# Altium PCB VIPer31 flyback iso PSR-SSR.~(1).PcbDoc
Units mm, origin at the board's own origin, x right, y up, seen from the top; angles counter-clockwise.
Board outline 152.4 x 101.6 mm, 2 copper layers (Top Layer, Bottom Layer); 56 components, 32 nets, 138 pads, 6 vias.
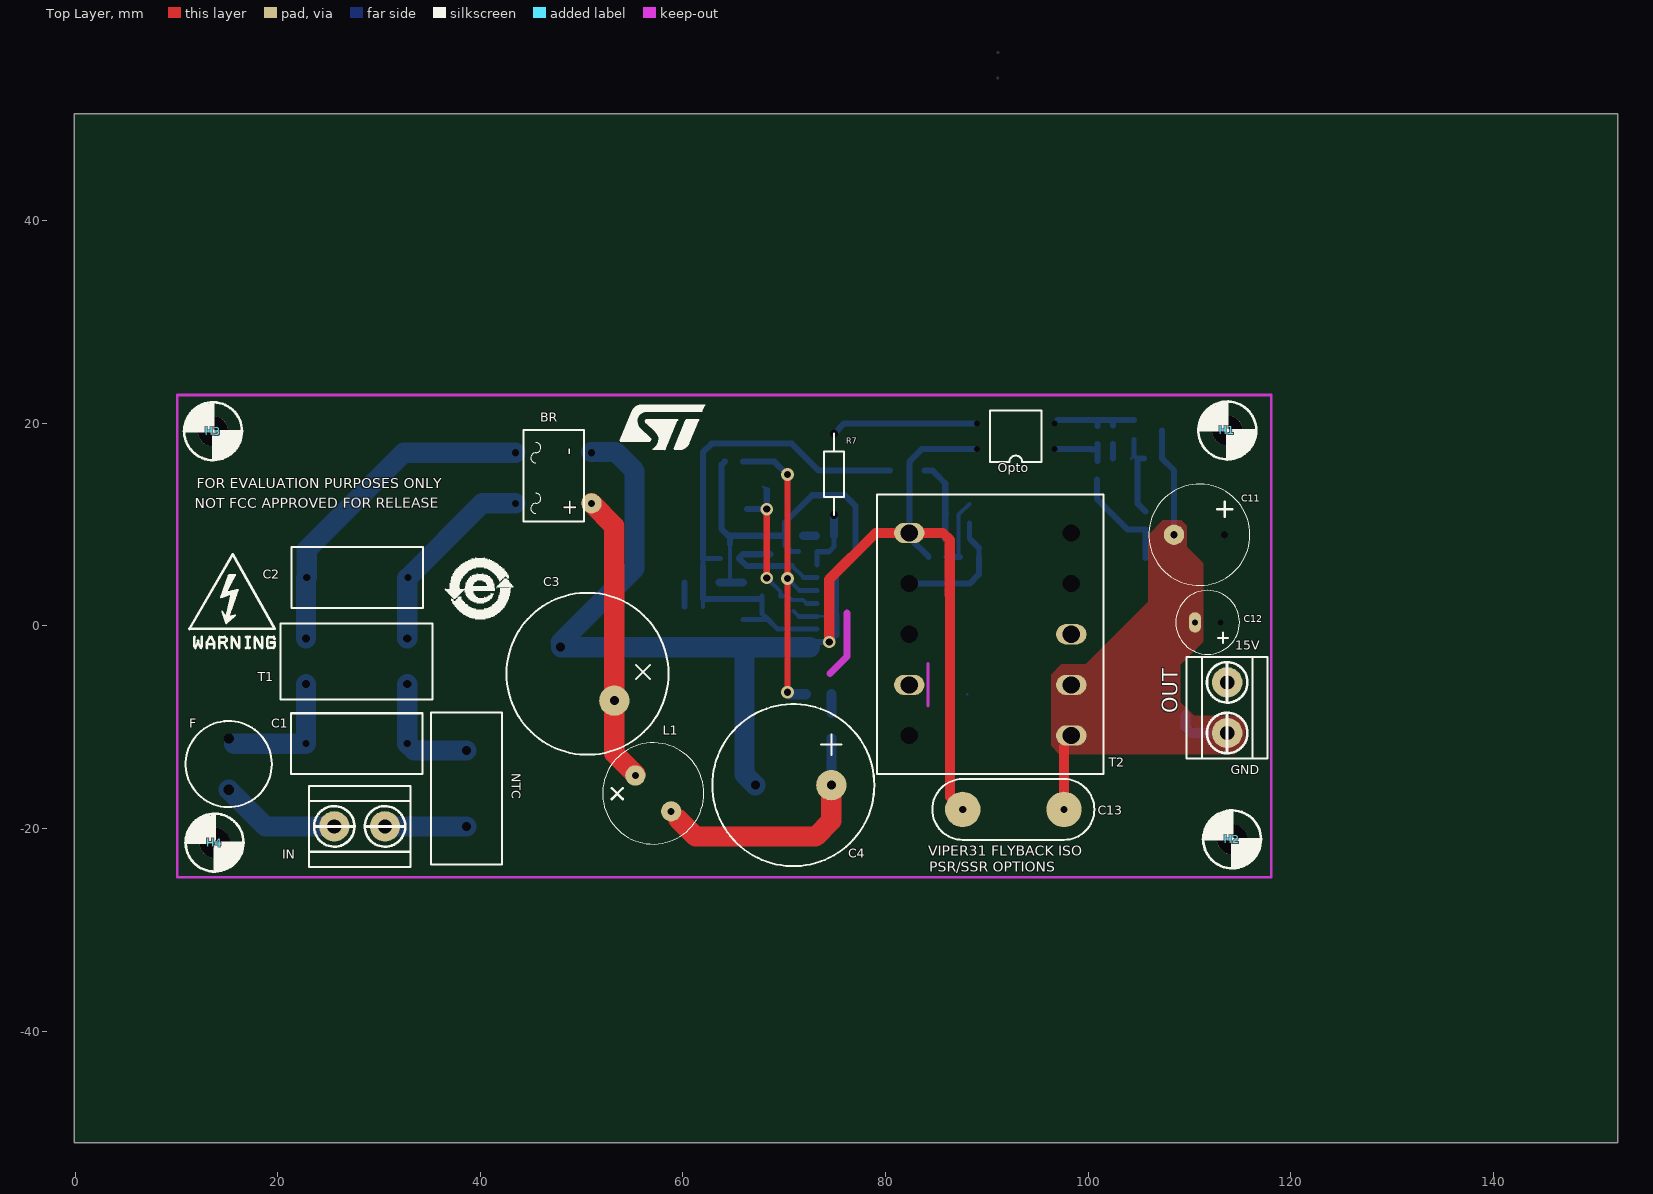
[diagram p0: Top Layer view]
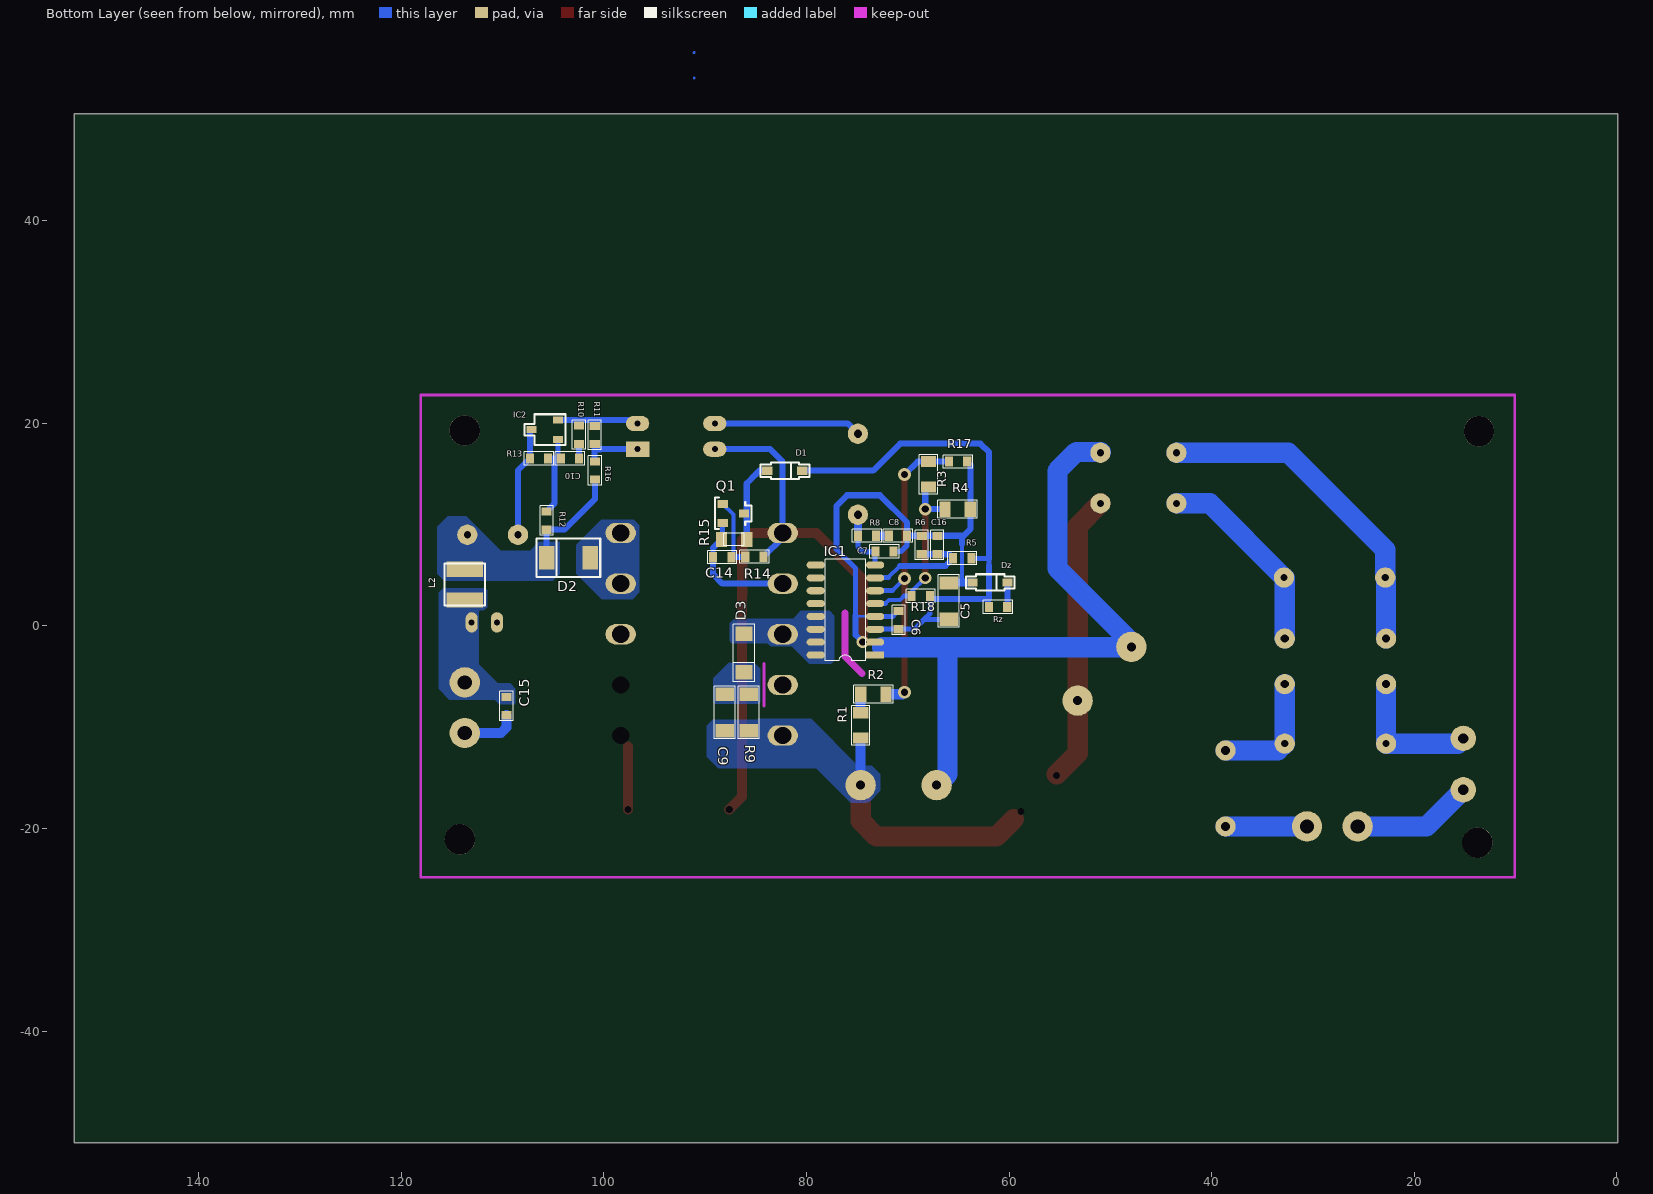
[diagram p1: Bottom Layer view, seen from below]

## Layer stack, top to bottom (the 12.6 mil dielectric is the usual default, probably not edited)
Top Solder: solder mask 0.0102, Solder Resist, Dk 3.5
Top Layer: signal copper 0.0356
Dielectric 1: dielectric 0.32, FR-4, Dk 4.8
Bottom Layer: signal copper 0.0356
Bottom Solder: solder mask 0.0102, Solder Resist, Dk 3.5

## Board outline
-0.1,-51.05 152.3,-51.05 152.3,50.55 -0.1,50.55

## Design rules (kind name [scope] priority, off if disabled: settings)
Clearance Clearance_1 [All] p1: gap=0.2 ignorepadtopadclearanceinfootprint=FALSE except(0: Arc-Hole Track-Hole SMDPad-Hole THPad-Hole Via-Hole Fill-Hole Poly-Hole Region-Hole Text-Hole)
Clearance [All] p2: gap=0.254 ignorepadtopadclearanceinfootprint=FALSE except(0: Arc-Poly Arc-Hole Track-Poly Track-Region Track-Hole SMDPad-Poly SMDPad-Hole THPad-Poly THPad-Hole Via-Poly Via-Hole Fill-Poly Fill-Hole Poly-Poly Poly-Hole Region-Hole Text-Hole)
PolygonConnect [All] p1: connectstyle=Direct reliefconductorwidth=0.254 reliefentries=4 polygonreliefangle="90 Angle" airgapwidth=0.254
RoutingVias [All] p1: holewidth=0.711 width=1.27 viastyle="Through Hole" minholewidth=0.711 minwidth=1.27 maxholewidth=0.711 maxwidth=1.27
SolderMaskExpansion [All] p1: expansion=0.102
Width [All] p1: maxlimit=2 minlimit=0.254 preferedwidth=0.254 minimp=50.000000 maximp=50.000000 favimp=50.000000
30 further rules are at their usual default settings.

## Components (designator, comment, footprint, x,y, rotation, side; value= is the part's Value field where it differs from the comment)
BR "MB6S-E3" BRIDGE 43.475,17.1 r270 top
C1 "100nF" CAP-13X6 32.775,-11.625 r180 top value="100 pF +/-5%, 250 Vdc"
C2 "100nF" CAP-13X6 32.85,4.775 r180 top value="100 pF +/-5%, 250 Vdc"
C3 "22 uF 400 Vcc" CAPOL-7.5X16 53.225,-7.375 r135 top value="68 uF +/-20%, 400 Vcc, +105°C"
C4 "22 uF 400 Vcc" CAPOL-7.5X16 74.65,-15.725 r180 top value="68 uF +/-20%, 400 Vcc, +105°C"
C5 "4.7uF" R-1206-B2 65.95,0.65 r90 top value="10uF +/-20%, 35 Vcc, +105°C"
C6 "100pF" R-0603-B2 70.9,-0.325 r90 top value="100 pF +/-5%, 250 Vdc"
C7 "1 nF 200 Vdc" R-0603-B2 73.2,7.35 r180 top value="1 nF +/-5%, 200 Vdc"
C8 "NC" R-0603-B2 71.875,8.9 r180 top
C9 "1nF +/-5% 630V" R-1206-B2 88.075,-10.35 r90 top value="1 nF 630 Vdc"
C10 "47nF" R-0603-B2 104.265,16.525 r180 top value="22nF, ±10%, 100Vcc"
C11 "680 uF, 25 Vcc" CAPOL-5X10#1 113.49,9 r180 top value="470 uF +/-20%, 35 Vcc, +105°C"
C12 "100 uF, 35 Vcc" CAPOL-2.5X6.3 113.065,0.35 r0 top value="100 uF +/-20%, 35 Vcc, +105°C"
C13 "2.2nF 250Vac X1 Y2" MYLAR-10X6 97.625,-18.125 r180 top value="2.2 nF 250 Vac X1 Y2"
C14 "NC" R-0603-B2 87.425,6.775 r0 top
C15 "100 nF" R-0603-B2 109.615,-7.025 r270 top value="100nF ±10%, 25 Vcc"
C16 "NC" R-0603-B2 67.075,7.075 r90 top
D1 "1N4148" SOD-123 83.875,15.325 r0 top value="1 A, 150 V"
D2 "STPS3150U" SMB-2 101.365,6.725 r180 top value="Schottky diode, 10A, 200 V"
D3 "MRA4007T3G" SMA-2 86.175,-0.775 r90 top
Dz "18V" SOD-123 63.6,4.3 r0 top value="18W, 500 mW"
F "2A" Fuse_3821200041_Wick 15.15,-16.18 r90 top
H1 "HOLE" FORO 113.75,19.3 r0 top
H2 "HOLE" FORO 114.225,-21.075 r0 top
H3 "HOLE" FORO 13.6,19.225 r0 top
H4 "HOLE" FORO 13.75,-21.4 r0 top
IC1 "VIPER31_SO16" SO-16N_2 73.225,-2.875 r90 top
IC2 "TS3431BILT" SOT23-3-MIRR 104.54,20.325 r270 top value="1.24 V VREF SHUNT"
IN "input connector" SM.2VITE 25.575,-19.8 r0 top
L1 "1mH" CAPOL-5X10#2 55.3,-14.775 r315 top value="3.3UH 3.23A 33 MOHM"
L2 "3.3 uH" WE_74404043033A_4x4 113.74,5.6 r90 top value="3.3UH 3.23A 33 MOHM"
NTC "10 Ohm" B57237S100M-NTC 38.625,-19.8 r90 top
Opto "SFH610A-2" DIP4 96.675,17.45 r180 top (schematic designator Opto1)
OUT "output connector" SM.2VITE 113.74,-5.575 r270 top
Q1 "BC807" BC817_NEW 88.275,10.3 r90 top value="PNP Transitstor 0.5A, 45 V, hfe 30"
R1 "3 MOhm" R-0805-B2 74.65,-8.575 r270 top value="1MOhm +/-5%"
R2 "3 MOhm" R-0805-B2 72.15,-6.75 r0 top value="1MOhm +/-5%"
R3 "6.8 kOhm" R-0805-B2 67.95,13.725 r90 top value="1MOhm +/-5%"
R4 "60.4 kOhm" R-0805-B2 63.825,11.525 r0 top value="1MOhm +/-5%"
R5 "NC" R-0603-B2 65.525,6.675 r180 top
R6 "0R" R-0603-B2 68.625,8.875 r270 top value="0 Ohm, 0.25W"
R7 "0R" RES-1/4W-3 74.925,18.975 r270 top value="0 Ohm, 0.25W"
R8 "NC" R-0603-B2 73.125,8.9 r0 top
R9 "220 kOhm" R-1206-B2 85.7,-6.75 r270 top value="220 KOhm +/-5%, 0.33W, 1206"
R10 "82k" R-0603-B2 102.465,17.975 r90 top value="470kO ±1%, 0.1W"
R11 "15k" R-0603-B2 100.915,19.75 r270 top value="22KO ±1%, 0.1W"
R12 "100 kOhm" R-0603-B2 105.665,11.3 r270 top value="130 kO ±1%, 0.1 W"
R13 "9 kOhm" R-0603-B2 107.315,16.525 r180 top value="15 kO ±1%, 0.1W, 0603"
R14 "NC" R-0603-B2 84.25,6.825 r0 top
R15 "10R" R-0805-B 88.4,8.525 r180 top value="10 Ohm, 0.1W"
R16 "2.2k" R-0603-B2 100.89,16.25 r270 top value="470O ±1%, 0.1W"
R17 "RESISTENZA" R-0603-B2 64.125,16.225 r0 top
R18 "RESISTENZA" R-0603-B2 69.625,2.95 r180 top
Rz "47R" R-0603-B2 60.175,1.875 r0 top value="47O ±1%, 0.125W"
T1 "2 X 10 mH" WE_744821110_Choke 32.775,-1.25 r90 top
T2 "Comment" "WURTH-EE25/10/6 VIPer31" 82.35,9.175 r0 top

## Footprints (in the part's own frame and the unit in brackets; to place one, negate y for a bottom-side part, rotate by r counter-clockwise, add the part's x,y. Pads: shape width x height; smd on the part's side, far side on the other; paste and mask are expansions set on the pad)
B57237S100M-NTC [mm]
  round 0 / inner round 0 / far side round 2 hole 0.9: 1(0,0) 2(7.5,0)
  silkscreen extent -3.75,-3.5 11.25,3.5
BC817_NEW [mm]
  rect 0.8x1 smd far side: 1(1.75,0) 2(-0.15,0) 3(0.8,2.1)
BRIDGE [mm]
  round 0 / inner round 0 / far side round 2 hole 0.7: 1(0,0) 3(5,0) 4(0,7.5)
  round 2 hole 0.7: 2(5,7.5)
  silkscreen extent -2.22,0.78 6.77,6.78
CAP-13X6 [mm]
  round 0 / inner round 0 / far side round 2 hole 0.7: 1(0,0) 2(10,0)
  silkscreen extent -1.5,-3 11.5,3
CAPOL-2.5X6.3 [mm]
  round 0 / inner round 0 / far side oval 1.2x2 hole 0.6: 1(0,0)
  oval 1.2x2 hole 0.6: 2(-2.5,0)
  silkscreen extent -4.4,-3.15 1.9,3.15
CAPOL-5X10#1 [mm]
  round 0 / inner round 0 / far side round 2 hole 0.7 unplated: 1(0,0)
  round 2 hole 0.7: 2(5,0)
  silkscreen extent -2.5,-5 7.5,5
CAPOL-5X10#2 [mm]
  round 2 / inner round 0 / far side round 0 hole 0.7: 1(0,0) 2(5,0)
  silkscreen extent -2.5,-5 7.5,5
CAPOL-7.5X16 [mm]
  round 3 hole 0.9: 1(0,0)
  round 0 / inner round 0 / far side round 3 hole 0.9: 2(7.5,0)
  silkscreen extent -4.25,-8 11.75,8
DIP4 [mm]
  rect 0x0 / inner rect 0x0 / far side rect 2.3x1.5 hole 0.6 unplated: 1(0,0)
  round 0 / inner round 0 / far side oval 2.3x1.5 hole 0.6 unplated: 2(0,-2.54) 3(7.62,-2.54) 4(7.62,0)
  silkscreen extent 1.27,-3.81 6.35,1.27
FORO [mm]
  round 3 hole 3: 1(0,0)
  silkscreen extent -2.88,-2.88 2.86,2.86
Fuse_3821200041_Wick [mm]
  round 0 / inner round 0 / far side round 2.5 hole 1: 1(0,0) 2(5.08,0)
  silkscreen extent -1.71,-4.25 6.79,4.25
MYLAR-10X6 [mm]
  round 3.5 / inner round 0 / far side round 0 hole 0.7: 1(0,0) 2(10,0)
  silkscreen extent -3,-3 13,3
R-0603-B2 [mm]
  rect 0.8x1 smd far side: 1(0,0) 2(1.8,0)
R-0805-B [mm]
  rect 1.1x1.5 smd far side: 1(0,0) 2(2.5,0)
R-0805-B2 [mm]
  rect 1.1x1.5 smd far side: 1(0,0) 2(2.5,0)
R-1206-B2 [mm]
  rect 1.3x1.8 smd far side: 1(0,0) 2(3.6,0)
RES-1/4W-3 [mm]
  round 0 / inner round 0 / far side round 2 hole 0.8: 1(0,0) 2(8,0)
  silkscreen extent 0,-1 8,1
SM.2VITE [mm]
  round 3 hole 1.4: 1(0,0) 2(5,0)
  silkscreen extent -2.5,-4 7.5,4
SMA-2 [mm]
  rect 1.45x1.65 smd far side: 1(0,0) 2(-3.8,0)
SMB-2 [mm]
  rect 1.52x2.3 smd far side: 1(0,0) 2(-4.3,0)
SO-16N_2 [mm]
  rect 0.7x1.8 smd far side: 1(0,0)
  oval 0.7x1.8 smd far side: 2(1.27,0) 3(2.54,0) 4(3.81,0) 5(5.08,0) 6(6.35,0) 7(7.62,0) 8(8.89,0) 9(8.89,-5.864) 10(7.62,-5.864) 11(6.35,-5.864) 12(5.08,-5.864) 13(3.81,-5.864) 14(2.54,-5.864) 15(1.27,-5.864) 16(0,-5.864)
SOD-123 [mm]
  rect 1x0.8 smd far side: 1(0,0) 2(-3.45,0)
SOT23-3-MIRR [mm]
  rect 0.7x1 smd far side: 1(1.9,0) 2(0.95,2.6) 3(0,0)
WE_744821110_Choke [mm]
  round 0 / inner round 0 / far side round 2 hole 0.8: 1(-4.5,0) 2(0,0) 3(0,10) 4(-4.5,10)
  silkscreen extent -6,-2.5 1.5,12.5
WE_74404043033A_4x4 [mm]
  rect 1.5x3.6 smd far side: 1(0,0) 2(-3.05,0)
"WURTH-EE25/10/6 VIPer31" [mm]
  oval 3x2 hole 1.7: 1(0,0) 4(0,-15) 8(16,-10)
  round 0 / inner round 0 / far side oval 3x2 hole 1.7: 2(0,-5) 3(0,-10) 5(0,-20) 9(16,-5) 10(16,0)
  oval 3x2 / inner round 0 / far side round 0 hole 1.7: 6(16,-20) 7(16,-15)
  silkscreen extent -3.17,-23.78 19.18,3.78

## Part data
BR: library part BRIDGE1, "Diode Bridge"
C1 C2 C6: library part CAP, "100 pF 250 Vdc multi layer capacitor", Package="SMD 0603", Part number=CGA3E3C0G2E101J080AA
C3 C4: library part "Cap Pol1", "Polarized Capacitor (Radial)", Package="TH D{}18 mm, H{}25 mm, P{}7.5 mm", Part number=400BXC68MEFC18X25
C5: library part "Cap Pol1", "Vcc cap 4.7uF 50 Vcc, Kemet", Package="TH D{}4 mm, H{}7 mm, P{}1.5 mm", Part number=35ML10MEFC4X7
C7: library part CAP, "1 nF 200 Vdc multi layer capacitor", Package="SMD 0603", Part number=C0603C102J2GACAUTO
C8 C14 C16: library part CAP, Package="SMD 0603"
C9: library part CAP, "1 nF 630 V multi layer capacitor", Package="SMD 1206", Part number=C3216C0G2J102J085AA
C10: library part CAP, "22 nF +/-10%, 100 Vcc, MLCC", Package="SMD 0603", Part number=GCM188R72A223KA37D
C11: library part "Cap Pol1", "470 uF +/-20%, 35 Vcc, +105°C", Package="TH D{}10 mm, H{}12.5 mm, P{}5 mm", Part number=25ZLH470MEFC10X12.5
C12: library part "Cap Pol1", "100 uF +/-20%, 35 Vcc, +105°C", Package="TH D{}6.3 mm, H{}11 mm, P{}2.5 mm", Part number=35ZLH100MEFC6.3X11
C13: library part CAP, "2.2 nF 2000 V single layer capacitor", Package="TH 8 mm X 5 mm, P 7.5 mm", Part number=DE2E3KY222MA2BM01F
C15: library part CAP, "100nF ±10%, 25 Vcc, MLCC", Package="SMD 0603", Part number=C0603C104K3RACTU
D1: library part Diode, "small signal diode", Part number=STPS1150A
D2: library part Diode, "Schottky diode, 10A, 200 V", Part number=STPS2200UF
D3: library part Diode, "Silicon Diode, 1 A, 1000 V"
Dz: library part "D Zener", "Zener Diode", Package="SOD 123", Part number=MMSZ5248B-V-GS08
F: library part "Fuse 1", "Fuse 2A,  250 Vca", Package="SMD 10.1mm X 1.43 mm", Part number=3403.0169.24
IC1: "Integrato"
IC2: library part TS432, "1.24 V VREF SHUNT", Package=SOT23-3, Part number=TS432ILT
IN OUT: library part M.2VITE, "Morsetti"
L1 L2: library part Inductor, "FIXED IND 3.3UH 3.23A 33 MOHM", Package="Lu x La: 0,157 x 0,157\" (4,00 x 4,00 mm)", Part number=74404043033A
NTC: library part Res2, Package="TH 9 mm X 4 mm , P 5mm", Part number=NTPA7100LBMB0
Opto: library part OPTO_1, "Opto ingresso 60 Vdc", Package="TH, DIP4"
Q1: library part PNP_BC807, "PNP Transitstor 0.5A, 45 V, hfe 30", Package=SOT23-3L, Part number=BC807-40LT3G
R1 R2: library part Res1, "3 MOhm +/-1%  0.125W, 0805 Vishay", Package="SMD 1206", Part number=ERJP08J105V
R3: library part Res1, "6.8 kOhm +/-1% 0.125W, 0805 Panasonic", Package="SMD 1206", Part number=ERJP08J105V
R4: library part Res1, "60.4 kOhm +/-1% 0.125W, 0805 Panasonic", Package="SMD 1206", Part number=ERJP08J105V
R5 R8 R14: library part Res1, "Not connected", Package="SMD 0603"
R6 R7: library part Res1, "0O, 0.25W, pkg 0603, serie CRCW", Package="SMD 0603", Part number=CRCW06030000Z0EAHP
R9: library part Res1, "220 KOhm +/-5%, 0.33W, 1206, serie ERJT08", Package="SMD 1206", Part number=ERJT08J224V
R10: library part Res1, "470kO ±1%, 0.1W", Package="SMD 0603", Part number=CRCW0603470KFKEA
R11: library part Res1, "22KO ±1%, 0.1W", Package="SMD 0603", Part number=CRCW060322K0FKEA
R12: library part Res1, "Not connected", Package="SMD 0603", Part number=CRCW0603130KFKEA
R13: library part Res1, "15 kO ±1%, 0.1W, 0603", Package="SMD 0603", Part number=CRG0603F15K
R15: library part Res1, "10O, 0.1W, pkg 0603, serie CRG0603", Package="SMD 0603", Part number=CRG0603F10R
R16: library part Res1, "470O ±1%, 0.1W", Package="SMD 0603", Part number=CRCW0603470RFKEA
R17 R18: "Resistor"
Rz: library part Res1, "47O ±1%, 0.125W", Package="SMD 0805", Part number=CRG0805F47R
T1: library part "CM CHOKE", "Common Mode Choke, Lo=10 mH, Rdc=350 mOhm, Idc=0.7A, Un=230 Vac", Package="TH D 15 mm X 7.5 mm", Part number=744821110

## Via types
v1: diameter 1.2, hole 0.7, Top Layer to Bottom Layer, 3 vias
v2: diameter 1.27, hole 0.711, Top Layer to Bottom Layer, 3 vias

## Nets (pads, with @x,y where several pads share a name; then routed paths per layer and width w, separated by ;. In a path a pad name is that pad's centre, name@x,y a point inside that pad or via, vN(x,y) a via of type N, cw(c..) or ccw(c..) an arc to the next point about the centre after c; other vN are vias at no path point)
15V: C12.1 C15.1 L2.2 OUT.1
GND: BR.4 C3.2 C4.2 C5.2 C6.2 C7.2 C8.2 C13.2 C16.2 Dz.1 IC1.1 IC1.2 IC1.4 Opto.4 R4.1 R6.1 R14.1 R17.1 T2.1 | length 181.8
  Top Layer w0.254: 86.375,-16.875 86.375,-16.625
  Top Layer w1: v1(74.445,-1.605) 74.445,4.595 79.025,9.175 T2.1 85.675,9.175 86.35,8.5 86.35,3.05 ; 86.375,-16.875 C13.2 ; 86.375,-16.625 86.375,3.325
  Bottom Layer w0.254: C3.2 C3.2@47.947,-2.097 ; 64.475,8.9 64.65,8.725 ; C5.2@65.9,4.3 C5.2 ; 72.528,-2.097 72.6,-2.025 ; IC1.4 75.06,0.935 75.15,1.025 ; T2.1@82.35,8.725 T2.1
  Bottom Layer w0.4: 64.65,4.325 64.65,8.1 ; C6.2 71.44,0.935
  Bottom Layer w0.5: C8.2 70.075,7.95 70.675,7.35 C7.2 ; 71.44,0.935 IC1.4 ; 75.15,1.025 75.15,5.675 77.05,7.575
  Bottom Layer w0.6: R17.1 63.825,15.925 R4.1 63.825,9.55 64.475,8.9 C8.2 70.075,10.225 72.75,12.9 75.984,12.9 77.05,11.834 77.05,7.575 ; 64.65,8.1 64.65,8.725 ; IC1.2 v1(74.445,-1.605) 75.15,-0.9 75.15,1.025 ; T2.1@82.35,8.725 R14.1 ; T2.1 82.35,16.2 83.6,17.45 Opto.4
  Bottom Layer w0.8: Dz.1 C5.2@65.9,4.3
  Bottom Layer w2: C3.2@47.922,-1.628 55.225,5.675 55.225,15.3 53.35,17.175 BR.4@50.95,17.175 ; C3.2@47.947,-2.097 66.075,-2.097 ; C4.2 66.075,-14.65 66.075,-2.097 ; 72.528,-2.097 66.075,-2.097
NetBR_1: BR.1 C2.2 T1.3 | length 33.4
  Bottom Layer w0.254: C2.2@22.775,4.7 C2.2
  Bottom Layer w2: T1.3 C2.2@22.775,4.7 ; C2.2 22.85,7.525 32.425,17.1 BR.1
NetBR_2: BR.2 C3.1 L1.1 | length 28.8
  Top Layer w0.254: 53.225,-12.575 53.225,-12.525 ; L1.1 L1.1@55.3,-14.65
  Top Layer w2: BR.2 53.225,9.85 C3.1 53.225,-12.525 ; 53.225,-12.575 L1.1@55.3,-14.65
  Bottom Layer w0.254: L1.1 55.3,-14.65
NetBR_3: BR.3 C2.1 T1.2 | length 19.7
  Bottom Layer w0.254: C2.1@32.775,4.7 C2.1
  Bottom Layer w2: T1.2 C2.1@32.775,4.7 ; C2.1 40.175,12.1 BR.3
NetC1_1: C1.1 NTC.2 T1.1 | length 12
  Bottom Layer w2: T1.1 C1.1 33.45,-12.3 NTC.2
NetC1_2: C1.2 F.2 T1.4 | length 13.7
  Bottom Layer w1: F.2 F.2@15.675,-11.625
  Bottom Layer w2: F.2@15.675,-11.625 C1.2 T1.4
NetC4_1: C4.1 C9.1 L1.2 R1.2 R9.2 T2.5 | length 24.6
  Top Layer w2: 59.548,-19.073 61.275,-20.8 73.1,-20.8 74.65,-19.25 C4.1
  Bottom Layer w1: C4.1 R1.2
NetC5_1: C5.1 C6.1 D1.2 IC1.3 R5.2 R18.2 Rz.2 | length 52.8
  Bottom Layer w0.254: 61.975,2.7 62,2.675 ; 61.975,6.6 62.05,6.675 ; 68.325,0.65 68.35,0.675 ; IC1.3@73.215,-0.325 IC1.3
  Bottom Layer w0.4: Rz.2 61.975,2.7
  Bottom Layer w0.5: 61.975,5.95 61.975,6.6 ; 62.05,6.675 R5.2 ; C5.1 68.325,0.65 ; R18.2 67.825,1.2 68.35,0.675 69.35,-0.325 C6.1 IC1.3@73.215,-0.325
  Bottom Layer w0.6: 61.975,2.7 61.975,5.95 ; 61.975,6.6 61.975,17.15 62.825,18 70.75,18 73.425,15.325 D1.2 ; 62,2.675 R18.2@67.625,2.675
NetC7_1: C7.1 IC1.8 R7.2 R8.2 | length 6.4
  Bottom Layer w0.254: IC1.8 IC1.8@73.272,6.062
  Bottom Layer w0.5: IC1.8@73.225,6.04 73.225,7.325 74.425,7.325 74.925,7.825 R8.2
  Bottom Layer w0.8: R8.2 R7.2
NetC8_1: C8.1 R8.1 | length 1.3
  Bottom Layer w0.8: C8.1 R8.1
NetC9_2: C9.2 D3.2 R9.1 | length 0
NetC10_1: C10.1 IC2.1 R12.1 R13.2 | length 8.2
  Bottom Layer w0.254: C10.1 C10.1@104.54,16.8
  Bottom Layer w0.5: C10.1@104.54,16.8 IC2.1
  Bottom Layer w0.6: R13.2 104.89,16.525 104.89,12.075 R12.1
NetC10_2: C10.2 R10.1 | length 1.4
  Bottom Layer w0.6: C10.2 R10.1
NetC11_1: C11.1 D2.2 L2.1 R12.2 R16.2 | length 10.7
  Bottom Layer w0.254: 103.89,9.5 103.89,9.525
  Bottom Layer w0.6: R16.2 100.89,12.525 103.89,9.525 ; 103.89,9.5 R12.2 D2.2
NetC14_1: C14.1 Q1.1 R14.2 | length 6.7
  Bottom Layer w0.254: C14.1@87.375,6.825 C14.1
  Bottom Layer w0.4: C14.1@87.225,7.15 87.225,11 ; 87.275,11.05 Q1.1
  Bottom Layer w0.6: R14.2 C14.1@87.375,6.825
NetC14_2: C14.2 Q1.2 R15.1 T2.2 | length 12.7
  Bottom Layer w0.254: R15.1@88.275,8.65 R15.1
  Bottom Layer w0.5: R15.1@88.275,8.65 Q1.2 ; C14.2 89.225,7.7
  Bottom Layer w0.6: T2.2 88.3,4.175 89.225,5.1 C14.2 ; R15.1 89.225,7.7
NetC16_1: C16.1 IC1.7 R5.1 R6.2 | length 11.8
  Bottom Layer w0.4: 70.775,5.925 71.93,4.77
  Bottom Layer w0.5: 71.93,4.77 IC1.7@73.225,4.77
  Bottom Layer w0.6: R6.2 C16.1 65.925,7.075 R5.1 66.275,5.925 70.775,5.925
NetD1_1: D1.1 Q1.3 R15.2 | length 8.4
  Bottom Layer w0.254: 85.875,14.1 85.9,14.075 ; Q1.3@85.9,11.075 85.925,11.1 Q1.3
  Bottom Layer w0.6: D1.1 84.65,15.325 85.013,14.963 85.875,14.1 ; R15.2 85.9,11.075 85.9,14.075
NetD2_1: D2.1 T2.9 T2.10
NetD3_1: D3.1 IC1.13 IC1.14 IC1.15 IC1.16 T2.3
NetDz_2: Dz.2 Rz.1 | length 2.4
  Bottom Layer w0.254: Rz.1@60.15,1.9 Rz.1
  Bottom Layer w0.6: Rz.1@60.15,1.9 Dz.2
NetF_1: F.1 IN.1 | length 11.9
  Bottom Layer w2: F.1 18.77,-19.8 IN.1
NetIC1_5: IC1.5 R3.1 R4.2 R18.1 | length 17.8
  Top Layer w0.6: v1(68.275,4.725) v1(68.275,11.525)
  Bottom Layer w0.254: R3.1 R3.1@68.275,13.4 ; v1@68.275,4.3 v1(68.275,4.725) ; IC1.5@73.22,2.2 IC1.5
  Bottom Layer w0.4: v1(68.275,4.725) 69.625,3.375 R18.1 ; 70.375,2.95 70.75,2.575 71.85,2.575 72.225,2.2
  Bottom Layer w0.5: R18.1 70.375,2.95 ; 72.225,2.2 IC1.5@73.22,2.2
  Bottom Layer w0.6: R4.2 v1(68.275,11.525) R3.1@68.275,13.4
NetIC1_6: IC1.6 R2.1 R3.2 R17.2 | length 31.7
  Top Layer w0.6: v2(70.325,-6.55) v2(70.325,4.675) v2(70.325,14.95)
  Bottom Layer w0.4: v2(70.325,4.675) 71.525,3.475
  Bottom Layer w0.5: 71.525,3.475 IC1.6
  Bottom Layer w0.6: R17.2 R3.2 69.025,16.225 v2@70.3,14.95
  Bottom Layer w1: v2(70.325,-6.55) 70.525,-6.75 R2.1
NetIC2_3: IC2.3 Opto.2 R10.2 R11.1 | length 9.2
  Bottom Layer w0.254: Opto.2 Opto.2@97.01,20.325 ; 100.9,20.325 100.915,20.31 ; R10.2@102.44,19.75 R10.2
  Bottom Layer w0.6: Opto.2@97.01,20.325 100.9,20.325 102.465,20.325 ; R11.1 100.915,20.31 ; R10.2 102.465,20.325 ; IC2.3 102.465,20.325
NetIN_2: IN.2 NTC.1 | length 8.1
  Bottom Layer w2: IN.2 NTC.1
NetOpto1_1: Opto.1 R11.2 R16.1 | length 6
  Bottom Layer w0.254: 100.325,17.45 100.34,17.435 ; R16.1 R16.1@100.915,16.275 ; 100.915,17.435 100.925,17.425
  Bottom Layer w0.6: Opto.1 100.325,17.45 ; 100.34,17.435 100.915,17.435 ; R16.1@100.915,16.275 100.915,17.435 ; R11.2 100.915,17.435
NetOpto1_3: Opto.3 R7.1 | length 14.6
  Bottom Layer w0.6: R7.1 75.94,19.99 Opto.3
NetR1_1: R1.1 R2.2 | length 1.8
  Bottom Layer w1: R1.1 R2.2
NetT2_3: 
SGND: C11.2 C12.2 C13.1 C15.2 IC2.2 OUT.2 R13.1 T2.6 T2.7 | length 23.1
  Top Layer w0.254: C12.2@110.54,0.025 C12.2@110.54,0.45
  Top Layer w1: C13.1 97.625,-11.9
  Bottom Layer w0.254: IC2.2 IC2.2@107.415,19.375
  Bottom Layer w0.6: R13.1 108.49,15.35 C11.2 ; R13.1@107.315,16.675 IC2.2@107.315,19.275
  Bottom Layer w1: C15.2 109.615,-10.015 110.175,-10.575 OUT.2
pads on no net: H1.1 H2.1 H3.1 H4.1 IC1.9 IC1.10 IC1.11 IC1.12 T2.4 T2.8
copper on no net: | length 0.1
  Bottom Layer w0.254: 91.07,54.1 91.095,54.075 ; 91.07,56.64 91.11,56.6

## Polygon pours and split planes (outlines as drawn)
NetC9_2 on Bottom Layer "Bottom Layer-No Net 1" (solid, pour order 60): 84.575,-4.225 85.175,-3.625 87.675,-3.625 89.225,-5.175 89.225,-7.5 89.05,-7.675 84.7,-7.675 84.575,-7.55
15V on Bottom Layer "Bottom Layer-No Net 1" (solid, pour order 50): 111.725,3.725 111.525,3.525 111.525,1.85 111.85,1.525 112.25,1.525 112.375,1.4 112.375,-3.8 110.5,-5.675 109.275,-5.675 108.75,-6.2 108.75,-7.49 108.69,-7.55 108.8,-7.66 108.8,-7.725 110.325,-7.725 110.775,-7.275 115.275,-7.275 116.325,-6.225 116.325,3.275 115.875,3.725
NetC11_1 on Bottom Layer "Bottom Layer-No Net 1" (solid, pour order 48): 104.375,5.125 105.05,4.45 115.75,4.45 116.45,5.15 116.45,9.775 115.4,10.825 113.6,10.825 110.2,7.425 107.3,7.425 106.425,8.3 104.425,8.3 104.375,8.25
NetD3_1 on Bottom Layer "Bottom Layer-No Net 1" (solid, pour order 46): 77.275,-3.45 77.575,-3.75 79.725,-3.75 81.45,-2.025 83.55,-2.025 83.875,-1.7 87.375,-1.7 87.6,-1.475 87.6,0.25 87.15,0.7 81.325,0.7 80.55,1.475 77.725,1.475 77.275,1.025
NetC4_1 on Bottom Layer "Bottom Layer-No Net 1" (solid, pour order 44): 75.65,-17.45 79.05,-14.05 88.725,-14.05 89.85,-12.925 89.85,-9.85 89.25,-9.25 84.875,-9.25 84.8,-9.175 79.55,-9.175 74.925,-13.8 73.55,-13.8 72.7,-14.65 72.7,-16.3 73.8,-17.4 74.125,-17.4 74.175,-17.45
NetD2_1 on Bottom Layer "Bottom Layer-No Net 1" (solid, pour order 42): 96.475,9.5 96.5,9.475 96.5,3.3 97.15,2.65 100.225,2.65 102.725,5.15 102.725,8.025 100.25,10.5 97.05,10.5 96.5,9.95 96.5,9.475
SGND on Top Layer "Bottom Layer-No Net 1" (solid, pour order 54): 96.35,-11.825 97.175,-12.65 114.5,-12.65 115.525,-11.625 115.525,-9.675 114.725,-8.875 110.475,-8.875 109.125,-7.525 109.125,-3.825 111.4,-1.55 111.4,6.175 109.75,7.825 109.75,9.9 109.2,10.45 107.4,10.45 105.925,8.975 105.925,2.375 99.75,-3.8 97.375,-3.8 96.35,-4.825

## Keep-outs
Keep-Out Layer:
  lines w0.254: 10.05,-24.8 118.1,-24.8 118.1,22.8 10.05,22.8 10.05,-24.8
  lines w0.3: 84.2,-7.925 84.2,-3.725
  lines w0.7: 74.525,-4.7 76.2,-3.025 ; 76.2,-2.925 76.2,1.275

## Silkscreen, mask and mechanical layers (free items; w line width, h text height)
Top Overlay:
  drawing of 11172 lines, arcs and shapes, not listed
  text "FOR EVALUATION PURPOSES ONLY" at 12,13.575 h1
  text "NOT FCC APPROVED FOR RELEASE" at 11.8,11.6 h1 r0.1
  text "15V" at 114.515,-2.65 h1.52
  text "GND" at 114.115,-14.95 h1.52
  text "VIPER31 FLYBACK ISO" at 84.225,-22.675 h1
  text "PSR/SSR OPTIONS" at 84.3,-24.275 h1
